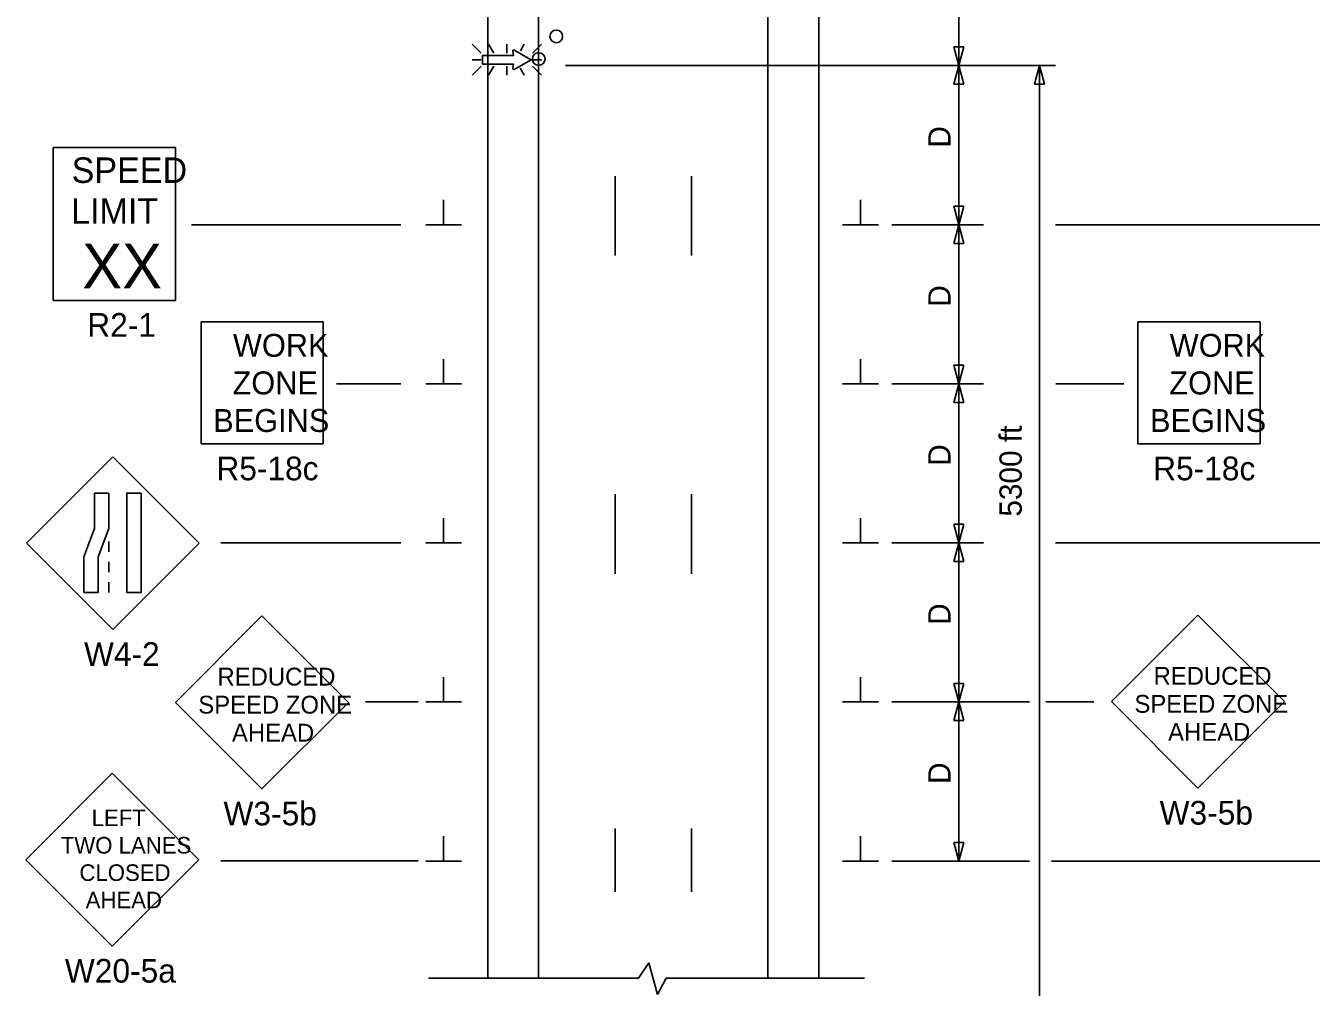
# Model space of a CAD drawing. Extents: x 16590 to 19508, y 5703 to 6974.
# Drawn here: x 17755.8 to 18159.8, y 6265.7 to 6568 of the extents above; entities that cross this region are included whole.
import ezdxf

# ---------------------------------------------------------------- set-up
doc = ezdxf.new("R2010")
doc.units = 0
for name, color, linetype in [('ALI_LEGAL_EX', 7, 'Continuous'), ('PAVT_EDGE_EX', 7, 'Continuous'), ('TRAFFIC_SIGNS_PR', 7, 'Continuous'), ('TYPICAL_TEXT_DIMEN_PR', 7, 'Continuous')]:
    doc.layers.add(name, color=color, linetype=linetype)

msp = doc.modelspace()

# ---------------------------------------------------------------- linework, layer by layer
at = {"layer": 'ALI_LEGAL_EX'}
for points in [[(17940.96, 6520.69), (17940.96, 6495.69)], [(17964.96, 6520.69), (17964.96, 6495.69)], [(17940.96, 6420.69), (17940.96, 6395.69)], [(17964.96, 6420.69), (17964.96, 6395.69)], [(17940.96, 6315.64), (17940.96, 6295.69)], [(17964.96, 6315.64), (17964.96, 6295.69)]]:
    msp.add_lwpolyline(points, dxfattribs=at)
at = {"layer": 'PAVT_EDGE_EX'}
for p, q in [((17900.96, 6925.33), (17900.96, 6268.58)), ((17916.96, 6925.33), (17916.96, 6268.58)), ((17988.96, 6925.33), (17988.96, 6268.58)), ((18004.96, 6925.33), (18004.96, 6268.58))]:
    msp.add_line(p, q, dxfattribs=at)
at = {"layer": 'TRAFFIC_SIGNS_PR'}
for p, q in [((17898.89, 6559.29), (17896.07, 6562.11)), ((17901.19, 6562.11), (17902.82, 6559.29)), ((17906.98, 6559.29), (17906.98, 6562.11)), ((17912.44, 6562.11), (17911.24, 6560.01)), ((17917.88, 6562.11), (17915.06, 6559.29)), ((17898.89, 6557.26), (17896.07, 6557.26)), ((17915.06, 6557.26), (17917.88, 6557.26)), ((17898.89, 6555.22), (17896.07, 6552.4)), ((17902.84, 6555.22), (17901.21, 6552.4)), ((17906.98, 6555.22), (17906.98, 6552.4)), ((17911.16, 6554.59), (17912.42, 6552.4)), ((17917.88, 6552.4), (17915.06, 6555.22)), ((17764.41, 6529.7), (17802.86, 6529.7)), ((17764.41, 6481.64), (17764.41, 6529.7)), ((17802.86, 6481.64), (17802.86, 6529.7)), ((17764.41, 6481.64), (17802.86, 6481.64)), ((17810.89, 6436.53), (17810.89, 6474.93)), ((17810.89, 6474.93), (17849.29, 6474.93)), ((17849.29, 6436.53), (17849.29, 6474.93)), ((18105.27, 6436.53), (18105.27, 6474.93)), ((18105.27, 6474.93), (18143.67, 6474.93)), ((18143.67, 6436.53), (18143.67, 6474.93)), ((17810.89, 6436.53), (17849.29, 6436.53)), ((18105.27, 6436.53), (18143.67, 6436.53)), ((17783.13, 6432.49), (17755.98, 6405.34)), ((17810.28, 6405.34), (17783.13, 6432.49)), ((17755.98, 6405.34), (17783.13, 6378.19)), ((17781.88, 6405.83), (17781.88, 6402.63)), ((17783.13, 6378.19), (17810.28, 6405.34)), ((17781.88, 6399.43), (17781.88, 6396.23)), ((17781.88, 6393.03), (17781.88, 6389.83)), ((17829.98, 6382.44), (17802.79, 6355.26)), ((17857.17, 6355.26), (17829.98, 6382.44)), ((18124.15, 6382.7), (18096.96, 6355.51)), ((18151.34, 6355.51), (18124.15, 6382.7)), ((17802.79, 6355.26), (17829.98, 6328.07)), ((17829.98, 6328.07), (17857.17, 6355.26)), ((18096.96, 6355.51), (18124.15, 6328.33)), ((18124.15, 6328.33), (18151.34, 6355.51)), ((17782.95, 6333.03), (17755.76, 6305.84)), ((17810.14, 6305.84), (17782.95, 6333.03)), ((17755.76, 6305.84), (17782.95, 6278.66)), ((17782.95, 6278.66), (17810.14, 6305.84))]:
    msp.add_line(p, q, dxfattribs=at)
for points in [[(17908.8, 6559.94), (17909.03, 6558.64), (17899.31, 6558.64), (17899.31, 6555.9), (17909.03, 6555.9), (17908.8, 6554.59)], [(17909.3, 6554.24), (17914.61, 6557.26), (17909.3, 6560.3)]]:
    msp.add_lwpolyline(points, dxfattribs=at)
for points in [[(17781.88, 6421.08), (17781.88, 6409.9), (17778.54, 6401.01), (17778.54, 6389.83), (17774.04, 6389.83), (17774.04, 6401.01), (17777.39, 6409.9), (17777.39, 6421.08)], [(17792.02, 6421.08), (17792.02, 6389.83), (17787.52, 6389.83), (17787.52, 6421.08)]]:
    msp.add_lwpolyline(points, close=True, dxfattribs=at)
for centre in [(17922.47, 6564.58), (17916.97, 6557.46)]:
    msp.add_circle(centre, 2, dxfattribs=at)
for centre, start, end in [((17909.14, 6560), 61.4833, 189.9593), ((17909.14, 6554.54), 170.7308, 298.8916)]:
    msp.add_arc(centre, 0.341, start, end, dxfattribs=at)
at = {"layer": 'TYPICAL_TEXT_DIMEN_PR'}
for p, q in [((18048.96, 6555.41), (18048.96, 6585.97)), ((18048.96, 6555.41), (18047.39, 6561.27)), ((18047.39, 6561.27), (18048.96, 6561.27)), ((18048.96, 6561.27), (18050.53, 6561.27)), ((18050.53, 6561.27), (18048.96, 6555.41)), ((17925.35, 6555.41), (18079.39, 6555.41)), ((17925.35, 6555.41), (18079.39, 6555.41)), ((18047.39, 6549.55), (18048.96, 6555.41)), ((18048.96, 6555.41), (18048.96, 6505.41)), ((18048.96, 6555.41), (18050.53, 6549.55)), ((18072.82, 6549.55), (18074.39, 6555.41)), ((18074.39, 6555.41), (18074.39, 6202.2)), ((18074.39, 6555.41), (18075.96, 6549.55)), ((18048.96, 6549.55), (18047.39, 6549.55)), ((18050.53, 6549.55), (18048.96, 6549.55)), ((18074.39, 6549.55), (18072.82, 6549.55)), ((18075.96, 6549.55), (18074.39, 6549.55)), ((17887.07, 6505.41), (17887.07, 6513.19)), ((18018.08, 6505.41), (18018.08, 6513.19)), ((18048.96, 6505.41), (18047.39, 6511.27)), ((18047.39, 6511.27), (18048.96, 6511.27)), ((18048.96, 6511.27), (18050.53, 6511.27)), ((18050.53, 6511.27), (18048.96, 6505.41)), ((17873.64, 6505.41), (17807.91, 6505.41)), ((17892.7, 6505.41), (17881.45, 6505.41)), ((18023.71, 6505.41), (18012.46, 6505.41)), ((18056.71, 6505.41), (18027.96, 6505.41)), ((18047.39, 6499.55), (18048.96, 6505.41)), ((18048.96, 6505.41), (18048.96, 6455.41)), ((18048.96, 6505.41), (18050.53, 6499.55)), ((18169.63, 6505.41), (18079.39, 6505.41)), ((18048.96, 6499.55), (18047.39, 6499.55)), ((18050.53, 6499.55), (18048.96, 6499.55)), ((17887.07, 6455.41), (17887.07, 6463.19)), ((18018.08, 6455.41), (18018.08, 6463.19)), ((18048.96, 6455.41), (18047.39, 6461.27)), ((18047.39, 6461.27), (18048.96, 6461.27)), ((18048.96, 6461.27), (18050.53, 6461.27)), ((18050.53, 6461.27), (18048.96, 6455.41)), ((17873.64, 6455.41), (17853.42, 6455.41)), ((17892.7, 6455.41), (17881.45, 6455.41)), ((18023.71, 6455.41), (18012.46, 6455.41)), ((18056.71, 6455.41), (18027.96, 6455.41)), ((18047.39, 6449.55), (18048.96, 6455.41)), ((18048.96, 6455.41), (18048.96, 6405.41)), ((18048.96, 6455.41), (18050.53, 6449.55)), ((18100.85, 6455.41), (18079.45, 6455.41)), ((18048.96, 6449.55), (18047.39, 6449.55)), ((18050.53, 6449.55), (18048.96, 6449.55)), ((17887.07, 6405.41), (17887.07, 6413.19)), ((18018.08, 6405.41), (18018.08, 6413.19)), ((18048.96, 6405.41), (18047.39, 6411.27)), ((18047.39, 6411.27), (18048.96, 6411.27)), ((18048.96, 6411.27), (18050.53, 6411.27)), ((18050.53, 6411.27), (18048.96, 6405.41)), ((17873.64, 6405.41), (17817.11, 6405.41)), ((17892.7, 6405.41), (17881.45, 6405.41)), ((18023.71, 6405.41), (18012.46, 6405.41)), ((18056.71, 6405.41), (18027.96, 6405.41)), ((18047.39, 6399.55), (18048.96, 6405.41)), ((18048.96, 6405.41), (18048.96, 6355.41)), ((18048.96, 6405.41), (18050.53, 6399.55)), ((18162.9, 6405.41), (18079.39, 6405.41)), ((18048.96, 6399.55), (18047.39, 6399.55)), ((18050.53, 6399.55), (18048.96, 6399.55)), ((17887.07, 6355.41), (17887.07, 6363.19)), ((18018.08, 6355.41), (18018.08, 6363.19)), ((18048.96, 6355.41), (18047.39, 6361.27)), ((18047.39, 6361.27), (18048.96, 6361.27)), ((18048.96, 6361.27), (18050.53, 6361.27)), ((18050.53, 6361.27), (18048.96, 6355.41)), ((17879.09, 6355.41), (17862.57, 6355.41)), ((17892.7, 6355.41), (17881.45, 6355.41)), ((18023.71, 6355.41), (18012.46, 6355.41)), ((18071.24, 6355.41), (18027.96, 6355.41)), ((18047.39, 6349.55), (18048.96, 6355.41)), ((18048.96, 6355.41), (18048.96, 6305.41)), ((18048.96, 6355.41), (18050.53, 6349.55)), ((18091.38, 6355.41), (18076.29, 6355.41)), ((18048.96, 6349.55), (18047.39, 6349.55)), ((18050.53, 6349.55), (18048.96, 6349.55)), ((17887.07, 6305.41), (17887.07, 6313.19)), ((18018.08, 6305.41), (18018.08, 6313.19)), ((18048.96, 6305.41), (18047.39, 6311.27)), ((18047.39, 6311.27), (18048.96, 6311.27)), ((18048.96, 6311.27), (18050.53, 6311.27)), ((18050.53, 6311.27), (18048.96, 6305.41)), ((17879.09, 6305.46), (17817.11, 6305.46)), ((17892.7, 6305.41), (17881.45, 6305.41)), ((18023.71, 6305.41), (18012.46, 6305.41)), ((18071.24, 6305.41), (18027.96, 6305.41)), ((18162.9, 6305.41), (18078.14, 6305.41)), ((17951.56, 6273.38), (17948.31, 6268.58)), ((17954.3, 6263.44), (17951.56, 6273.38)), ((17948.31, 6268.58), (17882.36, 6268.58)), ((17957.05, 6268.58), (17954.3, 6263.44)), ((18019.38, 6268.58), (17957.05, 6268.58))]:
    msp.add_line(p, q, dxfattribs=at)

# ---------------------------------------------------------------- texts
at = {"layer": 'TRAFFIC_SIGNS_PR'}
for s, height, p in [('SPEED', 8.01, (17770.19, 6518.55)), ('LIMIT', 8.01, (17770.03, 6505.73)), ('XX', 14.048, (17773.54, 6485.4)), ('R2-1', 7.449, (17775.11, 6470.19)), ('WORK', 7.217, (17820.89, 6463.89)), ('WORK', 7.217, (18115.27, 6463.89)), ('ZONE', 7.217, (17820.77, 6452.08)), ('ZONE', 7.217, (18115.15, 6452.08)), ('BEGINS', 7.217, (17814.7, 6440.27)), ('BEGINS', 7.217, (18109.08, 6440.27)), ('R5-18c', 7.44, (17815.7, 6425.09)), ('R5-18c', 7.44, (18110.08, 6425.09)), ('W4-2', 7.44, (17774.09, 6366.75)), ('REDUCED', 5.607, (17816.02, 6360.57)), ('REDUCED', 5.607, (18110.19, 6360.83)), ('SPEED ZONE', 5.607, (17810, 6351.76)), ('SPEED ZONE', 5.607, (18104.18, 6352.02)), ('AHEAD', 5.607, (17820.58, 6342.95)), ('AHEAD', 5.607, (18114.75, 6343.2)), ('W3-5b', 7.449, (17817.92, 6316.62)), ('W3-5b', 7.449, (18112.09, 6316.87)), ('LEFT', 5.206, (17776.48, 6316.39)), ('TWO LANES', 5.206, (17766.79, 6307.78)), ('CLOSED', 5.206, (17772.65, 6299.17)), ('AHEAD', 5.206, (17774.6, 6290.56)), ('W20-5a', 7.449, (17768.07, 6267.2))]:
    msp.add_text(s, height=height, dxfattribs=at).set_placement(p)
at = {"layer": 'TYPICAL_TEXT_DIMEN_PR'}
for s, p in [('D', (18046.4, 6529.63)), ('D', (18046.4, 6479.63)), ('5300 ft', (18068.76, 6413.65)), ('D', (18046.4, 6429.63)), ('D', (18046.4, 6379.63)), ('D', (18046.4, 6329.63))]:
    msp.add_text(s, height=7, rotation=90, dxfattribs=at).set_placement(p)

doc.saveas('drawing.dxf')
